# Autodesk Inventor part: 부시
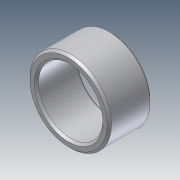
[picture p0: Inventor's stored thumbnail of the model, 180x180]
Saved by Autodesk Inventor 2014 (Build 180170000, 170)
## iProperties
Company: 한국ATC센터
Created: 2013-01
Part Number: 부시
Document SubType Name: Modeling
Designer: KYOUNG IL JANG
Density: 1 g/cm^3
Material: 일반
Appearance: 기본값
Author: KYOUNG IL JANG
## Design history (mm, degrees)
sketch "스케치1"
  geometry: L1 (15, 20)-(15, -46) reference; L2 (-20, 19)-(20, 19); L3 (30.7, -1)-(-30.7, -1) reference; L4 (19, 19)-(19, -1); L5 (15, -1)-(19, -1); L6 (0, 0)-(0, 19); L7 (19, 19)-(15, 19)
  constraints: 12 end point, 6 point on line, 1 collinear, 1 midpoint, 1 perpendicular, 1 vertical, 2 other
  dimensions: "d0" = 38 diameter of L4 L6; "d5" = 20 distance between parallel lines of L2 L3
revolve "회전1" sketch "스케치1" stored, may be unused: angle "d1" = 90 deg
chamfer "모따기1" distance "d2" = 1; stored, may be unused: second distance "d3" = 2, angle "d4" = 45 deg
node "솔리드1"
node "참조2"
